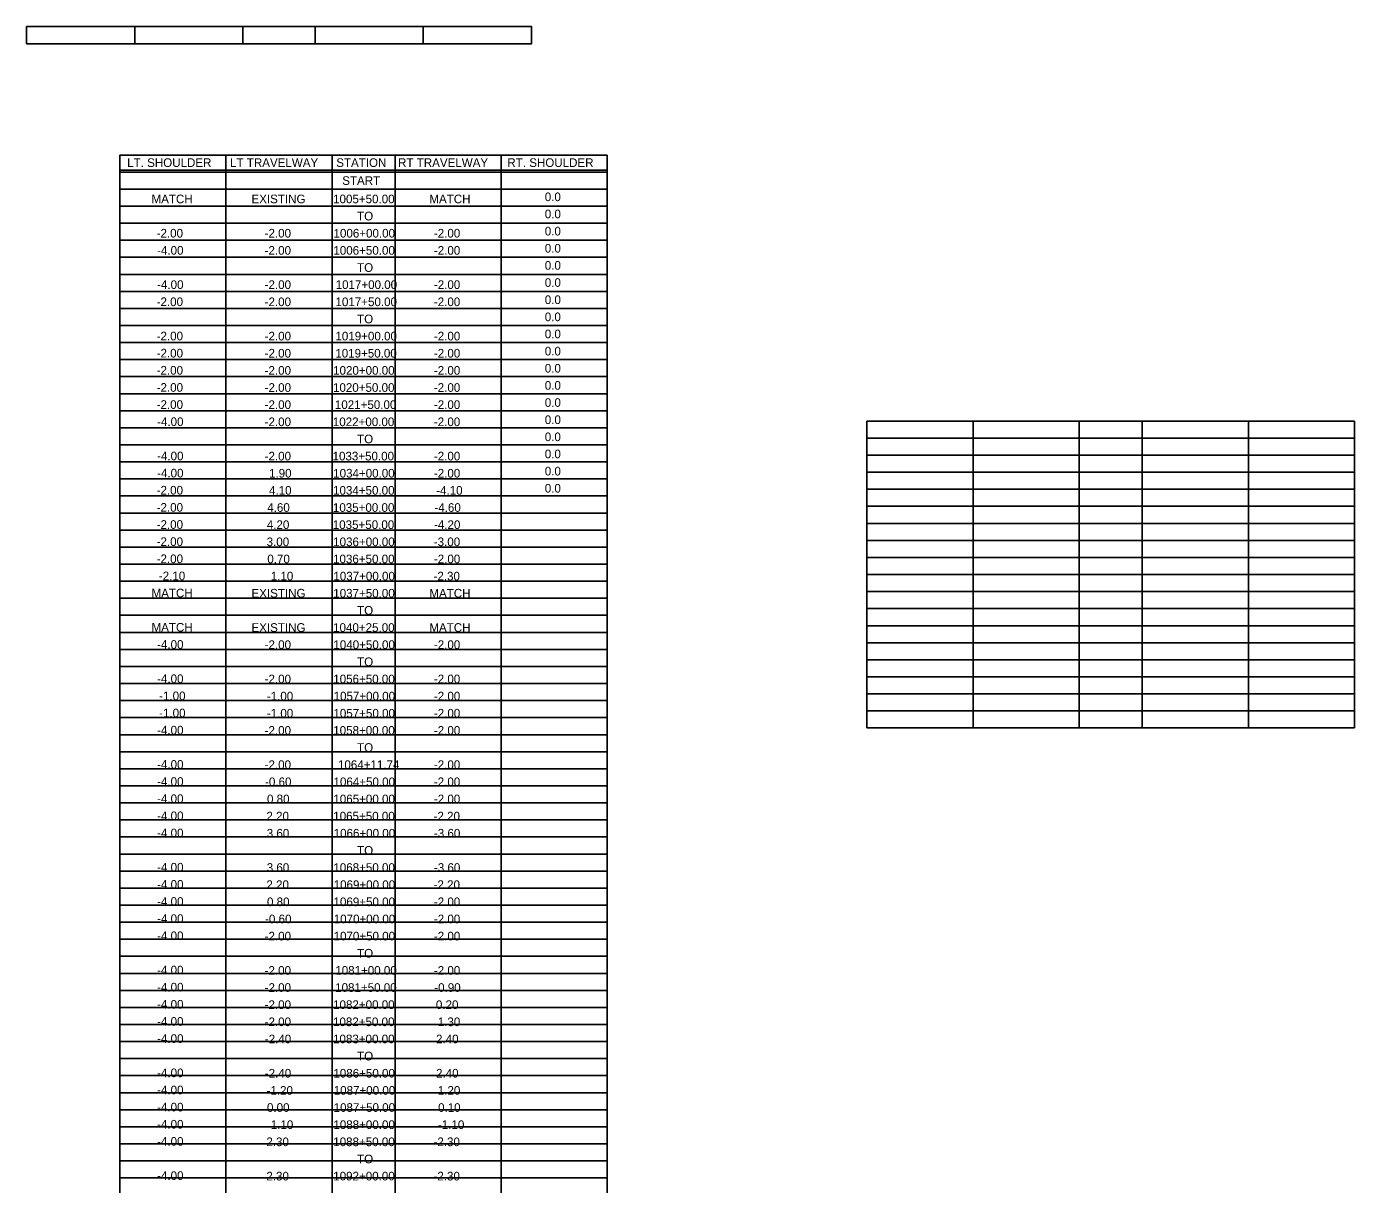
# Model space of a CAD drawing. Extents: x 1026502 to 1027102, y 781811 to 782040.
# Drawn here: x 1026795.8 to 1026869.5, y 781875.3 to 781939.5 of the extents above; entities that cross this region are included whole.
import ezdxf

# ---------------------------------------------------------------- set-up
doc = ezdxf.new("R2010")
doc.units = 0
doc.layers.add('BORDER', color=7, linetype='Continuous')
doc.layers.add('DIMENSIONS', color=7, linetype='Continuous')

msp = doc.modelspace()

# ---------------------------------------------------------------- linework, layer by layer
at = {"layer": 'BORDER'}
for p, q in [((1026798.834, 781939.541), (1026795.834, 781939.541)), ((1026798.834, 781938.59), (1026795.834, 781938.59)), ((1026798.834, 781938.59), (1026801.834, 781938.59)), ((1026801.005, 781932.416), (1026801.005, 781913.504)), ((1026801.005, 781932.416), (1026828.037, 781932.416)), ((1026801.005, 781932.416), (1026801.005, 781931.571)), ((1026806.888, 781932.416), (1026806.888, 781913.504)), ((1026812.771, 781932.416), (1026812.771, 781913.504)), ((1026816.271, 781932.416), (1026816.271, 781913.504)), ((1026822.154, 781932.416), (1026822.154, 781913.504)), ((1026828.037, 781932.416), (1026828.037, 781913.504)), ((1026801.005, 781931.571), (1026828.037, 781931.571)), ((1026801.005, 781931.47), (1026828.037, 781931.47)), ((1026801.005, 781930.525), (1026828.037, 781930.525)), ((1026801.005, 781929.579), (1026828.037, 781929.579)), ((1026801.005, 781928.633), (1026828.037, 781928.633)), ((1026801.005, 781927.688), (1026828.037, 781927.688)), ((1026801.005, 781926.742), (1026828.037, 781926.742)), ((1026801.005, 781925.797), (1026828.037, 781925.797)), ((1026801.005, 781924.851), (1026828.037, 781924.851)), ((1026801.005, 781923.905), (1026828.037, 781923.905)), ((1026801.005, 781922.96), (1026828.037, 781922.96)), ((1026801.005, 781922.014), (1026828.037, 781922.014)), ((1026801.005, 781921.069), (1026828.037, 781921.069)), ((1026801.005, 781920.123), (1026828.037, 781920.123)), ((1026801.005, 781919.177), (1026828.037, 781919.177)), ((1026801.005, 781918.232), (1026828.037, 781918.232)), ((1026842.432, 781917.658), (1026869.463, 781917.658)), ((1026842.432, 781917.658), (1026842.432, 781900.637)), ((1026848.315, 781917.658), (1026848.315, 781900.637)), ((1026854.198, 781917.658), (1026854.198, 781900.637)), ((1026857.698, 781917.658), (1026857.698, 781900.637)), ((1026863.58, 781917.658), (1026863.58, 781900.637)), ((1026869.463, 781917.658), (1026869.463, 781900.637)), ((1026801.005, 781917.286), (1026828.037, 781917.286)), ((1026801.005, 781916.341), (1026828.037, 781916.341)), ((1026842.432, 781916.712), (1026869.463, 781916.712)), ((1026801.005, 781915.395), (1026828.037, 781915.395)), ((1026842.432, 781915.767), (1026869.463, 781915.767)), ((1026842.432, 781914.821), (1026869.463, 781914.821)), ((1026801.005, 781914.449), (1026828.037, 781914.449)), ((1026801.005, 781914.449), (1026828.037, 781914.449)), ((1026842.432, 781913.875), (1026869.463, 781913.875)), ((1026801.005, 781913.504), (1026828.037, 781913.504)), ((1026801.005, 781913.504), (1026828.037, 781913.504)), ((1026801.005, 781913.504), (1026801.005, 781896.483)), ((1026806.888, 781913.504), (1026806.888, 781896.483)), ((1026812.771, 781913.504), (1026812.771, 781896.483)), ((1026816.271, 781913.504), (1026816.271, 781896.483)), ((1026822.154, 781913.504), (1026822.154, 781896.483)), ((1026828.037, 781913.504), (1026828.037, 781896.483)), ((1026801.005, 781912.558), (1026828.037, 781912.558)), ((1026842.432, 781912.93), (1026869.463, 781912.93)), ((1026842.432, 781911.984), (1026869.463, 781911.984)), ((1026801.005, 781911.613), (1026828.037, 781911.613)), ((1026842.432, 781911.039), (1026869.463, 781911.039)), ((1026801.005, 781910.667), (1026828.037, 781910.667)), ((1026801.005, 781909.721), (1026828.037, 781909.721)), ((1026842.432, 781910.093), (1026869.463, 781910.093)), ((1026801.005, 781908.776), (1026828.037, 781908.776)), ((1026842.432, 781909.147), (1026869.463, 781909.147)), ((1026842.432, 781908.202), (1026869.463, 781908.202)), ((1026801.005, 781907.83), (1026828.037, 781907.83)), ((1026842.432, 781907.256), (1026869.463, 781907.256)), ((1026801.005, 781906.885), (1026828.037, 781906.885)), ((1026801.005, 781905.939), (1026828.037, 781905.939)), ((1026842.432, 781906.311), (1026869.463, 781906.311)), ((1026801.005, 781904.993), (1026828.037, 781904.993)), ((1026842.432, 781905.365), (1026869.463, 781905.365)), ((1026842.432, 781904.419), (1026869.463, 781904.419)), ((1026801.005, 781904.048), (1026828.037, 781904.048)), ((1026801.005, 781903.102), (1026828.037, 781903.102)), ((1026842.432, 781903.474), (1026869.463, 781903.474)), ((1026801.005, 781902.157), (1026828.037, 781902.157)), ((1026842.432, 781902.528), (1026869.463, 781902.528)), ((1026842.432, 781901.583), (1026869.463, 781901.583)), ((1026801.005, 781901.211), (1026828.037, 781901.211)), ((1026842.432, 781900.637), (1026869.463, 781900.637)), ((1026801.005, 781900.265), (1026828.037, 781900.265)), ((1026801.005, 781899.32), (1026828.037, 781899.32)), ((1026801.005, 781898.374), (1026828.037, 781898.374)), ((1026801.005, 781897.429), (1026828.037, 781897.429)), ((1026801.005, 781896.483), (1026828.037, 781896.483)), ((1026801.005, 781896.483), (1026828.037, 781896.483)), ((1026801.005, 781896.483), (1026801.005, 781879.462)), ((1026806.888, 781896.483), (1026806.888, 781879.462)), ((1026812.771, 781896.483), (1026812.771, 781879.462)), ((1026816.271, 781896.483), (1026816.271, 781879.462)), ((1026822.154, 781896.483), (1026822.154, 781879.462)), ((1026828.037, 781896.483), (1026828.037, 781879.462)), ((1026801.005, 781895.537), (1026828.037, 781895.537)), ((1026801.005, 781894.592), (1026828.037, 781894.592)), ((1026801.005, 781893.646), (1026828.037, 781893.646)), ((1026801.005, 781892.701), (1026828.037, 781892.701)), ((1026801.005, 781891.755), (1026828.037, 781891.755)), ((1026801.005, 781890.809), (1026828.037, 781890.809)), ((1026801.005, 781889.864), (1026828.037, 781889.864)), ((1026801.005, 781888.918), (1026828.037, 781888.918)), ((1026801.005, 781887.973), (1026828.037, 781887.973)), ((1026801.005, 781887.027), (1026828.037, 781887.027)), ((1026801.005, 781886.081), (1026828.037, 781886.081)), ((1026801.005, 781885.136), (1026828.037, 781885.136)), ((1026801.005, 781884.19), (1026828.037, 781884.19)), ((1026801.005, 781883.245), (1026828.037, 781883.245)), ((1026801.005, 781882.299), (1026828.037, 781882.299)), ((1026801.005, 781881.353), (1026828.037, 781881.353)), ((1026801.005, 781880.408), (1026828.037, 781880.408)), ((1026801.005, 781879.462), (1026828.037, 781879.462)), ((1026801.005, 781879.462), (1026828.037, 781879.462)), ((1026801.005, 781879.462), (1026801.005, 781862.441)), ((1026806.888, 781879.462), (1026806.888, 781862.441)), ((1026812.771, 781879.462), (1026812.771, 781862.441)), ((1026816.271, 781879.462), (1026816.271, 781862.441)), ((1026822.154, 781879.462), (1026822.154, 781862.441)), ((1026828.037, 781879.462), (1026828.037, 781862.441)), ((1026801.005, 781878.517), (1026828.037, 781878.517)), ((1026801.005, 781877.571), (1026828.037, 781877.571)), ((1026801.005, 781876.625), (1026828.037, 781876.625)), ((1026801.005, 781875.68), (1026828.037, 781875.68))]:
    msp.add_line(p, q, dxfattribs=at)
for points in [[(1026795.834, 781939.541), (1026823.834, 781939.541), (1026823.834, 781938.59), (1026795.834, 781938.59)], [(1026801.005, 781931.47), (1026828.037, 781931.47), (1026828.037, 781913.504), (1026801.005, 781913.504)]]:
    msp.add_lwpolyline(points, close=True, dxfattribs=at)
for points in [[(1026807.834, 781939.541), (1026807.834, 781938.59), (1026801.834, 781938.59), (1026801.834, 781939.541)], [(1026811.834, 781939.541), (1026811.834, 781938.59), (1026807.834, 781938.59)], [(1026817.834, 781939.541), (1026817.834, 781938.59), (1026811.834, 781938.59), (1026811.834, 781939.541)], [(1026823.834, 781939.541), (1026823.834, 781938.59), (1026817.834, 781938.59), (1026817.834, 781939.541)]]:
    msp.add_lwpolyline(points, dxfattribs=at)

# ---------------------------------------------------------------- texts
at = {"layer": 'DIMENSIONS'}
for s, p in [('LT. SHOULDER', (1026801.414, 781931.753)), ('STATION', (1026813.005, 781931.753)), ('RT. SHOULDER', (1026822.494, 781931.753)), ('LT TRAVELWAY', (1026807.12, 781931.753)), ('RT TRAVELWAY', (1026816.435, 781931.753)), ('START', (1026813.337, 781930.757)), ('MATCH', (1026802.764, 781929.739)), ('EXISTING', (1026808.306, 781929.739)), ('1005+50.00', (1026812.832, 781929.739)), ('MATCH', (1026818.169, 781929.739)), ('0.0', (1026824.569, 781929.856)), ('0.0', (1026824.569, 781928.905)), ('TO', (1026814.162, 781928.788)), ('-2.00', (1026803.048, 781927.838)), ('-2.00', (1026809.036, 781927.837)), ('1006+00.00', (1026812.855, 781927.837)), ('-2.00', (1026818.419, 781927.837)), ('0.0', (1026824.569, 781927.955)), ('-4.00', (1026803.073, 781926.888)), ('-2.00', (1026809.036, 781926.886)), ('1006+50.00', (1026812.847, 781926.886)), ('-2.00', (1026818.419, 781926.886)), ('0.0', (1026824.569, 781927.004)), ('TO', (1026814.162, 781925.935)), ('0.0', (1026824.569, 781926.053)), ('-4.00', (1026803.073, 781924.987)), ('-2.00', (1026809.036, 781924.985)), ('1017+00.00', (1026812.972, 781924.985)), ('-2.00', (1026818.419, 781924.985)), ('0.0', (1026824.569, 781925.102)), ('-2.00', (1026803.048, 781924.036)), ('-2.00', (1026809.036, 781924.034)), ('1017+50.00', (1026812.965, 781924.034)), ('-2.00', (1026818.419, 781924.034)), ('0.0', (1026824.569, 781924.151)), ('TO', (1026814.162, 781923.083)), ('0.0', (1026824.569, 781923.2)), ('0.0', (1026824.569, 781922.25)), ('-2.00', (1026803.048, 781922.136)), ('-2.00', (1026809.036, 781922.132)), ('1019+00.00', (1026812.961, 781922.132)), ('-2.00', (1026818.419, 781922.132)), ('-2.00', (1026803.048, 781921.185)), ('-2.00', (1026809.036, 781921.181)), ('1019+50.00', (1026812.953, 781921.181)), ('-2.00', (1026818.419, 781921.181)), ('0.0', (1026824.569, 781921.299)), ('-2.00', (1026803.048, 781920.235)), ('-2.00', (1026809.036, 781920.23)), ('1020+00.00', (1026812.832, 781920.23)), ('-2.00', (1026818.419, 781920.23)), ('0.0', (1026824.569, 781920.348)), ('-2.00', (1026803.048, 781919.284)), ('-2.00', (1026809.036, 781919.28)), ('1020+50.00', (1026812.825, 781919.28)), ('-2.00', (1026818.419, 781919.28)), ('0.0', (1026824.569, 781919.397)), ('-2.00', (1026803.048, 781918.334)), ('-2.00', (1026809.036, 781918.329)), ('1021+50.00', (1026812.931, 781918.329)), ('-2.00', (1026818.419, 781918.329)), ('0.0', (1026824.569, 781918.446)), ('-4.00', (1026803.073, 781917.384)), ('-2.00', (1026809.036, 781917.378)), ('1022+00.00', (1026812.817, 781917.378)), ('-2.00', (1026818.419, 781917.378)), ('0.0', (1026824.569, 781917.495)), ('TO', (1026814.162, 781916.427)), ('0.0', (1026824.569, 781916.545)), ('0.0', (1026824.569, 781915.594)), ('-4.00', (1026803.073, 781915.483)), ('-2.00', (1026809.036, 781915.476)), ('1033+50.00', (1026812.802, 781915.476)), ('-2.00', (1026818.419, 781915.476)), ('-4.00', (1026803.073, 781914.532)), ('1.90', (1026809.278, 781914.525)), ('1034+00.00', (1026812.836, 781914.525)), ('-2.00', (1026818.419, 781914.525)), ('0.0', (1026824.569, 781914.643)), ('-2.00', (1026803.048, 781913.582)), ('4.10', (1026809.278, 781913.575)), ('1034+50.00', (1026812.829, 781913.575)), ('-4.10', (1026818.548, 781913.575)), ('0.0', (1026824.569, 781913.692)), ('-2.00', (1026803.048, 781912.632)), ('4.60', (1026809.18, 781912.624)), ('1035+00.00', (1026812.821, 781912.624)), ('-4.60', (1026818.449, 781912.624)), ('-2.00', (1026803.048, 781911.681)), ('4.20', (1026809.157, 781911.673)), ('1035+50.00', (1026812.813, 781911.673)), ('-4.20', (1026818.427, 781911.673)), ('-2.00', (1026803.048, 781910.731)), ('3.00', (1026809.146, 781910.722)), ('1036+00.00', (1026812.836, 781910.722)), ('-3.00', (1026818.415, 781910.722)), ('-2.00', (1026803.048, 781909.78)), ('0.70', (1026809.184, 781909.771)), ('1036+50.00', (1026812.829, 781909.771)), ('-2.00', (1026818.419, 781909.771)), ('-2.10', (1026803.168, 781908.83)), ('1.10', (1026809.376, 781908.82)), ('1037+00.00', (1026812.847, 781908.82)), ('-2.30', (1026818.4, 781908.82)), ('MATCH', (1026802.764, 781907.88)), ('EXISTING', (1026808.306, 781907.87)), ('1037+50.00', (1026812.84, 781907.87)), ('MATCH', (1026818.169, 781907.87)), ('TO', (1026814.162, 781906.919)), ('MATCH', (1026802.764, 781905.979)), ('EXISTING', (1026808.306, 781905.968)), ('1040+25.00', (1026812.832, 781905.968)), ('MATCH', (1026818.169, 781905.968)), ('-4.00', (1026803.073, 781905.028)), ('-2.00', (1026809.036, 781905.017)), ('1040+50.00', (1026812.847, 781905.017)), ('-2.00', (1026818.419, 781905.017)), ('TO', (1026814.162, 781904.066)), ('-4.00', (1026803.073, 781903.128)), ('-2.00', (1026809.036, 781903.115)), ('1056+50.00', (1026812.84, 781903.115)), ('-2.00', (1026818.419, 781903.115)), ('-1.00', (1026803.185, 781902.177)), ('-1.00', (1026809.157, 781902.165)), ('1057+00.00', (1026812.859, 781902.165)), ('-2.00', (1026818.419, 781902.165)), ('-1.00', (1026803.185, 781901.227)), ('-1.00', (1026809.157, 781901.214)), ('1057+50.00', (1026812.851, 781901.214)), ('-2.00', (1026818.419, 781901.214)), ('-4.00', (1026803.073, 781900.276)), ('-2.00', (1026809.036, 781900.263)), ('1058+00.00', (1026812.84, 781900.263)), ('-2.00', (1026818.419, 781900.263)), ('TO', (1026814.162, 781899.312)), ('-4.00', (1026803.073, 781898.376)), ('-2.00', (1026809.036, 781898.361)), ('1064+11.74', (1026813.101, 781898.361)), ('-2.00', (1026818.419, 781898.361)), ('-4.00', (1026803.073, 781897.425)), ('-0.60', (1026809.059, 781897.41)), ('1064+50.00', (1026812.855, 781897.41)), ('-2.00', (1026818.419, 781897.41)), ('-4.00', (1026803.073, 781896.475)), ('0.80', (1026809.165, 781896.46)), ('1065+00.00', (1026812.847, 781896.46)), ('-2.00', (1026818.419, 781896.46)), ('-4.00', (1026803.073, 781895.524)), ('2.20', (1026809.134, 781895.509)), ('1065+50.00', (1026812.84, 781895.509)), ('-2.20', (1026818.404, 781895.509)), ('-4.00', (1026803.073, 781894.574)), ('3.60', (1026809.153, 781894.558)), ('1066+00.00', (1026812.863, 781894.558)), ('-3.60', (1026818.423, 781894.558)), ('TO', (1026814.162, 781893.607)), ('-4.00', (1026803.073, 781892.673)), ('3.60', (1026809.153, 781892.656)), ('1068+50.00', (1026812.847, 781892.656)), ('-3.60', (1026818.423, 781892.656)), ('-4.00', (1026803.073, 781891.723)), ('2.20', (1026809.134, 781891.705)), ('1069+00.00', (1026812.863, 781891.705)), ('-2.20', (1026818.404, 781891.705)), ('-4.00', (1026803.073, 781890.772)), ('0.80', (1026809.165, 781890.755)), ('1069+50.00', (1026812.855, 781890.755)), ('-2.00', (1026818.419, 781890.755)), ('-4.00', (1026803.073, 781889.822)), ('-0.60', (1026809.059, 781889.804)), ('1070+00.00', (1026812.866, 781889.804)), ('-2.00', (1026818.419, 781889.804)), ('-4.00', (1026803.073, 781888.872)), ('-2.00', (1026809.036, 781888.853)), ('1070+50.00', (1026812.859, 781888.853)), ('-2.00', (1026818.419, 781888.853)), ('TO', (1026814.162, 781887.902)), ('-4.00', (1026803.073, 781886.971)), ('-2.00', (1026809.036, 781886.951)), ('1081+00.00', (1026812.953, 781886.951)), ('-2.00', (1026818.419, 781886.951)), ('-4.00', (1026803.073, 781886.02)), ('-2.00', (1026809.036, 781886)), ('1081+50.00', (1026812.946, 781886)), ('-0.90', (1026818.442, 781886)), ('-4.00', (1026803.073, 781885.07)), ('-2.00', (1026809.036, 781885.05)), ('1082+00.00', (1026812.832, 781885.05)), ('0.20', (1026818.532, 781885.05)), ('-4.00', (1026803.073, 781884.12)), ('-2.00', (1026809.036, 781884.099)), ('1082+50.00', (1026812.825, 781884.099)), ('1.30', (1026818.635, 781884.099)), ('-4.00', (1026803.073, 781883.169)), ('-2.40', (1026809.044, 781883.148)), ('1083+00.00', (1026812.829, 781883.148)), ('2.40', (1026818.54, 781883.148)), ('TO', (1026814.162, 781882.197)), ('-4.00', (1026803.073, 781881.268)), ('-2.40', (1026809.044, 781881.246)), ('1086+50.00', (1026812.847, 781881.246)), ('2.40', (1026818.54, 781881.246)), ('-4.00', (1026803.073, 781880.318)), ('-1.20', (1026809.142, 781880.295)), ('1087+00.00', (1026812.866, 781880.295)), ('1.20', (1026818.638, 781880.295)), ('-4.00', (1026803.073, 781879.368)), ('0.00', (1026809.165, 781879.345)), ('1087+50.00', (1026812.859, 781879.345)), ('0.10', (1026818.653, 781879.345)), ('-4.00', (1026803.073, 781878.417)), ('1.10', (1026809.376, 781878.394)), ('1088+00.00', (1026812.847, 781878.394)), ('-1.10', (1026818.646, 781878.394)), ('-4.00', (1026803.073, 781877.467)), ('2.30', (1026809.131, 781877.443)), ('1088+50.00', (1026812.84, 781877.443)), ('-2.30', (1026818.4, 781877.443)), ('TO', (1026814.162, 781876.492)), ('-4.00', (1026803.073, 781875.566)), ('2.30', (1026809.131, 781875.541)), ('1092+00.00', (1026812.84, 781875.541)), ('-2.30', (1026818.4, 781875.541))]:
    msp.add_text(s, height=0.48, dxfattribs=at).set_placement(p)

doc.saveas('drawing.dxf')
